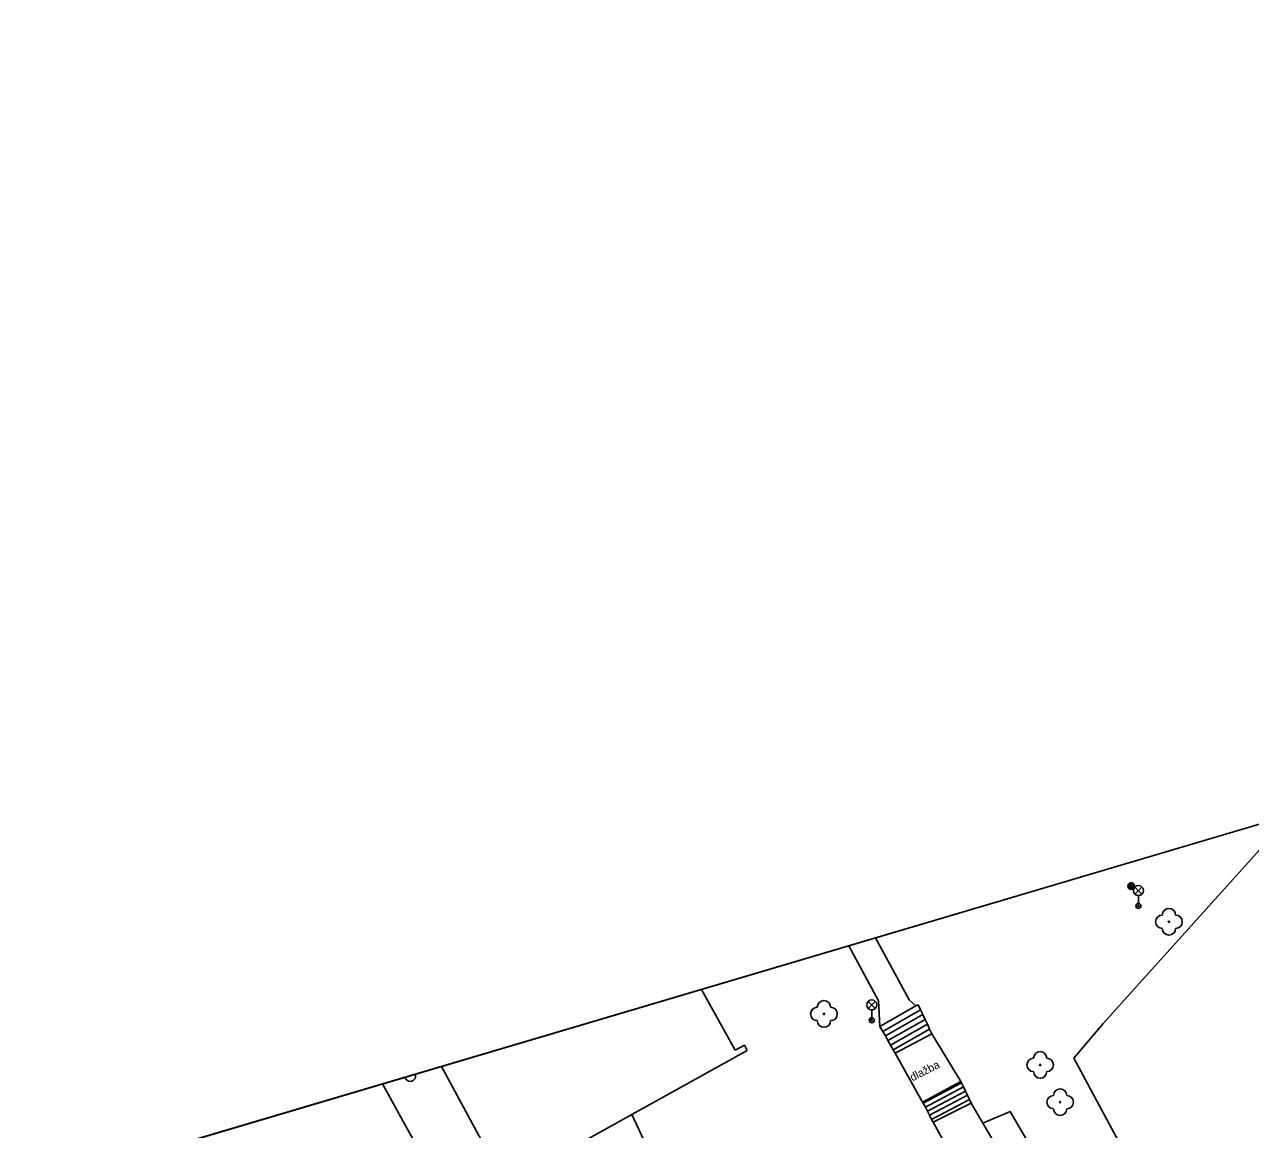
# Model space of a CAD drawing. Extents: x -493753 to -49290, y -1127285 to -112654.
# Drawn here: x -493245.2 to -493153.3, y -1126618.6 to -1126535.7 of the extents above; entities that cross this region are included whole.
import ezdxf

# ---------------------------------------------------------------- set-up
doc = ezdxf.new("R2010")
doc.units = 0
for name, color, linetype in [('Vrstva 1', 7, 'Continuous'), ('Vrstva 10', 7, 'Continuous'), ('Vrstva 11', 7, 'Continuous'), ('Vrstva 21', 7, 'Continuous'), ('Vrstva 22', 7, 'Continuous'), ('Vrstva 25', 7, 'Continuous'), ('Vrstva 33', 7, 'Continuous'), ('Vrstva 36', 7, 'Continuous'), ('Vrstva 40', 7, 'Continuous'), ('Vrstva 5', 7, 'Continuous'), ('Vrstva 60', 7, 'Continuous'), ('Vrstva 7', 7, 'Continuous'), ('Vrstva 8', 7, 'Continuous')]:
    doc.layers.add(name, color=color, linetype=linetype)

msp = doc.modelspace()

# ---------------------------------------------------------------- linework, layer by layer
at = {"layer": 'Vrstva 1'}
msp.add_line((-492950.39, -1126535.73), (-493753.129, -1126773.634), dxfattribs=at)
at = {"layer": 'Vrstva 10'}
for p, q in [((-493181.367, -1126604.184), (-493178.86, -1126608.84)), ((-493183.383, -1126604.781), (-493181.15, -1126608.91)), ((-493181.05, -1126610.84), (-493181.15, -1126608.91)), ((-493178.86, -1126608.84), (-493178.35, -1126609.28))]:
    msp.add_line(p, q, dxfattribs=at)
for points in [[(-493178, -1126609.58), (-493178.17, -1126609.22), (-493178.35, -1126609.28)], [(-493177.83, -1126609.94), (-493178, -1126609.58)], [(-493177.66, -1126610.31), (-493177.83, -1126609.94)], [(-493180.84, -1126611.21), (-493181.05, -1126610.84)], [(-493177.49, -1126610.67), (-493177.66, -1126610.31)], [(-493177.32, -1126611.03), (-493177.49, -1126610.67)], [(-493180.64, -1126611.55), (-493180.84, -1126611.21)], [(-493180.45, -1126611.9), (-493180.64, -1126611.55)], [(-493174.99, -1126614.95), (-493177.15, -1126611.39), (-493177.32, -1126611.03)], [(-493180.25, -1126612.24), (-493180.45, -1126611.9)], [(-493180.05, -1126612.59), (-493180.25, -1126612.24)], [(-493179.9, -1126612.85), (-493180.05, -1126612.59)], [(-493177.85, -1126616.5), (-493179.9, -1126612.85)], [(-493174.93, -1126615.07), (-493174.99, -1126614.95)], [(-493174.78, -1126615.37), (-493174.93, -1126615.07)], [(-493174.64, -1126615.68), (-493174.78, -1126615.37)], [(-493174.49, -1126615.99), (-493174.64, -1126615.68)], [(-493174.34, -1126616.3), (-493174.49, -1126615.99)], [(-493174.2, -1126616.59), (-493174.34, -1126616.3)], [(-493177.8, -1126616.59), (-493177.85, -1126616.5)], [(-493177.64, -1126616.89), (-493177.8, -1126616.59)], [(-493177.49, -1126617.19), (-493177.64, -1126616.89)], [(-493177.33, -1126617.49), (-493177.49, -1126617.19)], [(-493170.91, -1126622.19), (-493173.33, -1126618.08), (-493174.2, -1126616.59)], [(-493177.17, -1126617.8), (-493177.33, -1126617.49)], [(-493177.05, -1126618.02), (-493177.17, -1126617.8)], [(-493173.81, -1126623.91), (-493173.89, -1126623.77), (-493177.05, -1126618.02)]]:
    msp.add_lwpolyline(points, dxfattribs=at)
at = {"layer": 'Vrstva 11'}
for p, q in [((-493178, -1126609.58), (-493180.84, -1126611.21)), ((-493177.83, -1126609.94), (-493180.64, -1126611.55)), ((-493177.66, -1126610.31), (-493180.45, -1126611.9)), ((-493177.49, -1126610.67), (-493180.25, -1126612.24)), ((-493177.32, -1126611.03), (-493180.05, -1126612.59))]:
    msp.add_line(p, q, dxfattribs=at)
for points in [[(-493178.35, -1126609.28), (-493181.05, -1126610.84)], [(-493179.9, -1126612.85), (-493177.15, -1126611.39)], [(-493177.85, -1126616.5), (-493174.99, -1126614.95)], [(-493177.8, -1126616.59), (-493174.93, -1126615.07)], [(-493177.64, -1126616.89), (-493174.78, -1126615.37)], [(-493177.49, -1126617.19), (-493174.64, -1126615.68)], [(-493177.33, -1126617.49), (-493174.49, -1126615.99)], [(-493177.17, -1126617.8), (-493174.34, -1126616.3)], [(-493177.05, -1126618.02), (-493174.2, -1126616.59)]]:
    msp.add_lwpolyline(points, dxfattribs=at)
at = {"layer": 'Vrstva 21'}
msp.add_lwpolyline([(-493163.32, -1126636.03), (-493159.17, -1126634.32), (-493165.2, -1126623.01), (-493167.65, -1126623.44), (-493171.29, -1126617.21), (-493173.33, -1126618.08)], dxfattribs=at)
at = {"layer": 'Vrstva 22'}
for centre in [(-493159.37, -1126602.99), (-493185.24, -1126609.9), (-493169.03, -1126613.72), (-493167.53, -1126616.51)]:
    msp.add_circle(centre, 0.05, dxfattribs=at)
for centre, start, end in [((-493159.87, -1126602.99), 90, 270), ((-493159.37, -1126602.49), 360, 180), ((-493158.87, -1126602.99), 270, 90), ((-493159.37, -1126603.49), 180, 0), ((-493185.24, -1126609.4), 360, 180), ((-493185.74, -1126609.9), 90, 270), ((-493184.74, -1126609.9), 270, 90), ((-493185.24, -1126610.4), 180, 0), ((-493169.03, -1126613.22), 360, 180), ((-493169.53, -1126613.72), 90, 270), ((-493168.53, -1126613.72), 270, 90), ((-493169.03, -1126614.22), 180, 0), ((-493168.03, -1126616.51), 90, 270), ((-493167.53, -1126616.01), 360, 180), ((-493167.03, -1126616.51), 270, 90), ((-493167.53, -1126617.01), 180, 0)]:
    msp.add_arc(centre, 0.5, start, end, dxfattribs=at)
at = {"layer": 'Vrstva 25'}
for radius in [0.25, 0.158, 0.05]:
    msp.add_circle((-493162.2, -1126600.31), radius, dxfattribs=at)
at = {"layer": 'Vrstva 33'}
for p, q in [((-493161.925, -1126600.385), (-493161.395, -1126600.915)), ((-493161.925, -1126600.915), (-493161.395, -1126600.385)), ((-493161.66, -1126601.8), (-493161.66, -1126601.025)), ((-493181.925, -1126608.955), (-493181.395, -1126609.485)), ((-493181.925, -1126609.485), (-493181.395, -1126608.955)), ((-493181.66, -1126610.37), (-493181.66, -1126609.595))]:
    msp.add_line(p, q, dxfattribs=at)
for centre, radius in [((-493161.66, -1126600.65), 0.375), ((-493161.66, -1126601.8), 0.19), ((-493161.66, -1126601.8), 0.05), ((-493181.66, -1126609.22), 0.375), ((-493181.66, -1126610.37), 0.19), ((-493181.66, -1126610.37), 0.05)]:
    msp.add_circle(centre, radius, dxfattribs=at)
at = {"layer": 'Vrstva 36'}
msp.add_line((-493215.882, -1126614.413), (-493216.654, -1126614.642), dxfattribs=at)
msp.add_arc((-493216.262, -1126614.547), 0.403, 193.56306, 19.453, dxfattribs=at)
at = {"layer": 'Vrstva 5'}
for p, q in [((-493191.2, -1126612.25), (-493191.9, -1126612.61)), ((-493191, -1126612.63), (-493191.2, -1126612.25))]:
    msp.add_line(p, q, dxfattribs=at)
for points in [[(-493191.9, -1126612.61), (-493194.435, -1126608.057)], [(-493191, -1126612.63), (-493199.64, -1126617.43), (-493209.11, -1126622.7), (-493213.932, -1126613.835)]]:
    msp.add_lwpolyline(points, dxfattribs=at)
at = {"layer": 'Vrstva 60'}
msp.add_line((-493125, -1126587.478), (-493750, -1126772.707), dxfattribs=at)
at = {"layer": 'Vrstva 7'}
for points in [[(-493149.32, -1126643.08), (-493150.27, -1126640.82), (-493154.93, -1126633.96), (-493155.18, -1126633.59), (-493161.73, -1126622.08), (-493166.5, -1126613.22), (-493164.27, -1126610.59), (-493151.62, -1126596.53)], [(-493216.82, -1126617.9), (-493218.341, -1126615.142)], [(-493199.64, -1126617.43), (-493198.38, -1126620.15), (-493211.8, -1126627.7)]]:
    msp.add_lwpolyline(points, dxfattribs=at)
at = {"layer": 'Vrstva 8'}
msp.add_lwpolyline([(-493214.27, -1126622.51), (-493216.82, -1126617.9)], dxfattribs=at)

# ---------------------------------------------------------------- texts
at = {"layer": 'Vrstva 40'}
msp.add_text('dlažba', height=0.6, rotation=26.89136, dxfattribs=at).set_placement((-493178.612, -1126614.96))

doc.saveas('drawing.dxf')
